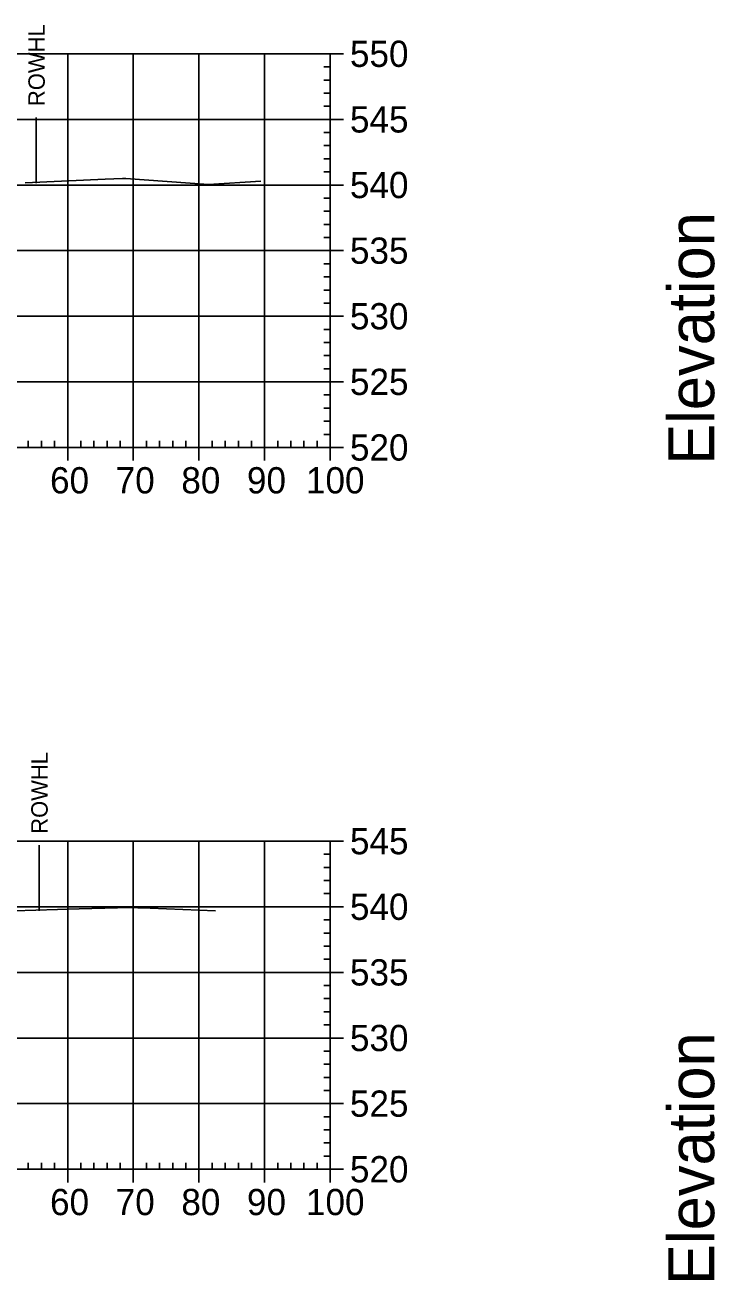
# Model space of a CAD drawing. Extents: x 708103 to 717568, y 374476 to 378707.
# Drawn here: x 708830.5 to 708935.6, y 377747.8 to 377939 of the extents above; entities that cross this region are included whole.
import ezdxf

# ---------------------------------------------------------------- set-up
doc = ezdxf.new("R2010")
doc.units = 0
for name, color, linetype in [('57', 7, 'Continuous'), ('60', 7, 'Continuous'), ('Existing', 7, 'Continuous'), ('XS_Right_of_Way', 7, 'Continuous')]:
    doc.layers.add(name, color=color, linetype=linetype)

msp = doc.modelspace()

# ---------------------------------------------------------------- linework, layer by layer
at = {"layer": '57'}
for p, q in [((708676.98, 377934.63), (708876.98, 377934.63)), ((708836.98, 377874.63), (708836.98, 377934.63)), ((708846.98, 377874.63), (708846.98, 377934.63)), ((708856.98, 377874.63), (708856.98, 377934.63)), ((708866.98, 377874.63), (708866.98, 377934.63)), ((708876.98, 377874.63), (708876.98, 377934.63)), ((708876.98, 377874.63), (708876.98, 377934.63)), ((708878.98, 377934.63), (708876.98, 377934.63)), ((708876.98, 377932.63), (708875.98, 377932.63)), ((708876.98, 377930.63), (708875.98, 377930.63)), ((708876.98, 377928.63), (708875.98, 377928.63)), ((708876.98, 377926.63), (708875.98, 377926.63)), ((708676.98, 377924.63), (708876.98, 377924.63)), ((708878.98, 377924.63), (708876.98, 377924.63)), ((708876.98, 377922.63), (708875.98, 377922.63)), ((708876.98, 377920.63), (708875.98, 377920.63)), ((708876.98, 377918.63), (708875.98, 377918.63)), ((708876.98, 377916.63), (708875.98, 377916.63)), ((708676.98, 377914.63), (708876.98, 377914.63)), ((708878.98, 377914.63), (708876.98, 377914.63)), ((708876.98, 377912.63), (708875.98, 377912.63)), ((708876.98, 377910.63), (708875.98, 377910.63)), ((708876.98, 377908.63), (708875.98, 377908.63)), ((708876.98, 377906.63), (708875.98, 377906.63)), ((708676.98, 377904.63), (708876.98, 377904.63)), ((708878.98, 377904.63), (708876.98, 377904.63)), ((708876.98, 377902.63), (708875.98, 377902.63)), ((708876.98, 377900.63), (708875.98, 377900.63)), ((708876.98, 377898.63), (708875.98, 377898.63)), ((708876.98, 377896.63), (708875.98, 377896.63)), ((708676.98, 377894.63), (708876.98, 377894.63)), ((708878.98, 377894.63), (708876.98, 377894.63)), ((708876.98, 377892.63), (708875.98, 377892.63)), ((708876.98, 377890.63), (708875.98, 377890.63)), ((708876.98, 377888.63), (708875.98, 377888.63)), ((708876.98, 377886.63), (708875.98, 377886.63)), ((708676.98, 377884.63), (708876.98, 377884.63)), ((708878.98, 377884.63), (708876.98, 377884.63)), ((708876.98, 377882.63), (708875.98, 377882.63)), ((708876.98, 377880.63), (708875.98, 377880.63)), ((708876.98, 377878.63), (708875.98, 377878.63)), ((708830.98, 377874.63), (708830.98, 377875.63)), ((708832.98, 377874.63), (708832.98, 377875.63)), ((708834.98, 377874.63), (708834.98, 377875.63)), ((708838.98, 377874.63), (708838.98, 377875.63)), ((708840.98, 377874.63), (708840.98, 377875.63)), ((708842.98, 377874.63), (708842.98, 377875.63)), ((708844.98, 377874.63), (708844.98, 377875.63)), ((708848.98, 377874.63), (708848.98, 377875.63)), ((708850.98, 377874.63), (708850.98, 377875.63)), ((708852.98, 377874.63), (708852.98, 377875.63)), ((708854.98, 377874.63), (708854.98, 377875.63)), ((708858.98, 377874.63), (708858.98, 377875.63)), ((708860.98, 377874.63), (708860.98, 377875.63)), ((708862.98, 377874.63), (708862.98, 377875.63)), ((708864.98, 377874.63), (708864.98, 377875.63)), ((708868.98, 377874.63), (708868.98, 377875.63)), ((708870.98, 377874.63), (708870.98, 377875.63)), ((708872.98, 377874.63), (708872.98, 377875.63)), ((708874.98, 377874.63), (708874.98, 377875.63)), ((708876.98, 377876.63), (708875.98, 377876.63)), ((708676.98, 377874.63), (708876.98, 377874.63)), ((708676.98, 377874.63), (708876.98, 377874.63)), ((708836.98, 377872.63), (708836.98, 377874.63)), ((708846.98, 377872.63), (708846.98, 377874.63)), ((708856.98, 377872.63), (708856.98, 377874.63)), ((708866.98, 377872.63), (708866.98, 377874.63)), ((708876.98, 377872.63), (708876.98, 377874.63)), ((708878.98, 377874.63), (708876.98, 377874.63)), ((708676.98, 377814.63), (708876.98, 377814.63)), ((708836.98, 377764.63), (708836.98, 377814.63)), ((708846.98, 377764.63), (708846.98, 377814.63)), ((708856.98, 377764.63), (708856.98, 377814.63)), ((708866.98, 377764.63), (708866.98, 377814.63)), ((708876.98, 377764.63), (708876.98, 377814.63)), ((708876.98, 377764.63), (708876.98, 377814.63)), ((708878.98, 377814.63), (708876.98, 377814.63)), ((708876.98, 377812.63), (708875.98, 377812.63)), ((708876.98, 377810.63), (708875.98, 377810.63)), ((708876.98, 377808.63), (708875.98, 377808.63)), ((708876.98, 377806.63), (708875.98, 377806.63)), ((708676.98, 377804.63), (708876.98, 377804.63)), ((708878.98, 377804.63), (708876.98, 377804.63)), ((708876.98, 377802.63), (708875.98, 377802.63)), ((708876.98, 377800.63), (708875.98, 377800.63)), ((708876.98, 377798.63), (708875.98, 377798.63)), ((708876.98, 377796.63), (708875.98, 377796.63)), ((708676.98, 377794.63), (708876.98, 377794.63)), ((708878.98, 377794.63), (708876.98, 377794.63)), ((708876.98, 377792.63), (708875.98, 377792.63)), ((708876.98, 377790.63), (708875.98, 377790.63)), ((708876.98, 377788.63), (708875.98, 377788.63)), ((708876.98, 377786.63), (708875.98, 377786.63)), ((708676.98, 377784.63), (708876.98, 377784.63)), ((708878.98, 377784.63), (708876.98, 377784.63)), ((708876.98, 377782.63), (708875.98, 377782.63)), ((708876.98, 377780.63), (708875.98, 377780.63)), ((708876.98, 377778.63), (708875.98, 377778.63)), ((708876.98, 377776.63), (708875.98, 377776.63)), ((708676.98, 377774.63), (708876.98, 377774.63)), ((708878.98, 377774.63), (708876.98, 377774.63)), ((708876.98, 377772.63), (708875.98, 377772.63)), ((708876.98, 377770.63), (708875.98, 377770.63)), ((708876.98, 377768.63), (708875.98, 377768.63)), ((708876.98, 377766.63), (708875.98, 377766.63)), ((708676.98, 377764.63), (708876.98, 377764.63)), ((708676.98, 377764.63), (708876.98, 377764.63)), ((708830.98, 377764.63), (708830.98, 377765.63)), ((708832.98, 377764.63), (708832.98, 377765.63)), ((708834.98, 377764.63), (708834.98, 377765.63)), ((708836.98, 377762.63), (708836.98, 377764.63)), ((708838.98, 377764.63), (708838.98, 377765.63)), ((708840.98, 377764.63), (708840.98, 377765.63)), ((708842.98, 377764.63), (708842.98, 377765.63)), ((708844.98, 377764.63), (708844.98, 377765.63)), ((708846.98, 377762.63), (708846.98, 377764.63)), ((708848.98, 377764.63), (708848.98, 377765.63)), ((708850.98, 377764.63), (708850.98, 377765.63)), ((708852.98, 377764.63), (708852.98, 377765.63)), ((708854.98, 377764.63), (708854.98, 377765.63)), ((708856.98, 377762.63), (708856.98, 377764.63)), ((708858.98, 377764.63), (708858.98, 377765.63)), ((708860.98, 377764.63), (708860.98, 377765.63)), ((708862.98, 377764.63), (708862.98, 377765.63)), ((708864.98, 377764.63), (708864.98, 377765.63)), ((708866.98, 377762.63), (708866.98, 377764.63)), ((708868.98, 377764.63), (708868.98, 377765.63)), ((708870.98, 377764.63), (708870.98, 377765.63)), ((708872.98, 377764.63), (708872.98, 377765.63)), ((708874.98, 377764.63), (708874.98, 377765.63)), ((708876.98, 377762.63), (708876.98, 377764.63)), ((708878.98, 377764.63), (708876.98, 377764.63))]:
    msp.add_line(p, q, dxfattribs=at)
at = {"layer": 'Existing'}
for points in [[(708830.48, 377914.97), (708842.7, 377915.53), (708845.33, 377915.62), (708845.83, 377915.61), (708858.45, 377914.69), (708866.4, 377915.23)], [(708825.47, 377803.9), (708838.75, 377804.33), (708844.56, 377804.49), (708845.81, 377804.52), (708849.54, 377804.43), (708859.48, 377804.01)]]:
    msp.add_lwpolyline(points, dxfattribs=at)
at = {"layer": 'XS_Right_of_Way'}
for p, q in [((708832.17, 377924.91), (708832.17, 377914.91)), ((708832.61, 377814), (708832.61, 377804))]:
    msp.add_line(p, q, dxfattribs=at)

# ---------------------------------------------------------------- texts
at = {"layer": '57'}
for s, p in [('550', (708879.98, 377932.63)), ('545', (708879.98, 377922.63)), ('540', (708879.98, 377912.63)), ('535', (708879.98, 377902.63)), ('530', (708879.98, 377892.63)), ('525', (708879.98, 377882.63)), ('520', (708879.98, 377872.63)), ('60', (708834.29, 377867.63)), ('70', (708844.29, 377867.63)), ('80', (708854.29, 377867.63)), ('90', (708864.29, 377867.63)), ('100', (708873.28, 377867.63)), ('545', (708879.98, 377812.63)), ('540', (708879.98, 377802.63)), ('535', (708879.98, 377792.63)), ('530', (708879.98, 377782.63)), ('525', (708879.98, 377772.63)), ('520', (708879.98, 377762.63)), ('60', (708834.29, 377757.63)), ('70', (708844.29, 377757.63)), ('80', (708854.29, 377757.63)), ('90', (708864.29, 377757.63)), ('100', (708873.28, 377757.63))]:
    msp.add_text(s, height=4, dxfattribs=at).set_placement(p)
at = {"layer": '60'}
for p in [(708935.48, 377871.99), (708935.48, 377746.99)]:
    msp.add_text('Elevation', height=7, rotation=90, dxfattribs=at).set_placement(p)
at = {"layer": 'XS_Right_of_Way'}
for p in [(708833.49, 377926.67), (708833.93, 377815.76)]:
    msp.add_text('ROWHL', height=2.5, rotation=90, dxfattribs=at).set_placement(p)

doc.saveas('drawing.dxf')
